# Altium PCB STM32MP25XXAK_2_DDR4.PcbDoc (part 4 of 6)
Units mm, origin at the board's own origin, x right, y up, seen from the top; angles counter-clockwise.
Board outline 120 x 79.6 mm, 4 copper layers (Top Layer, Signal Layer 1, Signal Layer 2, Bottom Layer), stack 1.614 mm thick; 243 components, 152 nets, 1304 pads, 784 vias.
Unrouted connection lines stored in the file: 6.
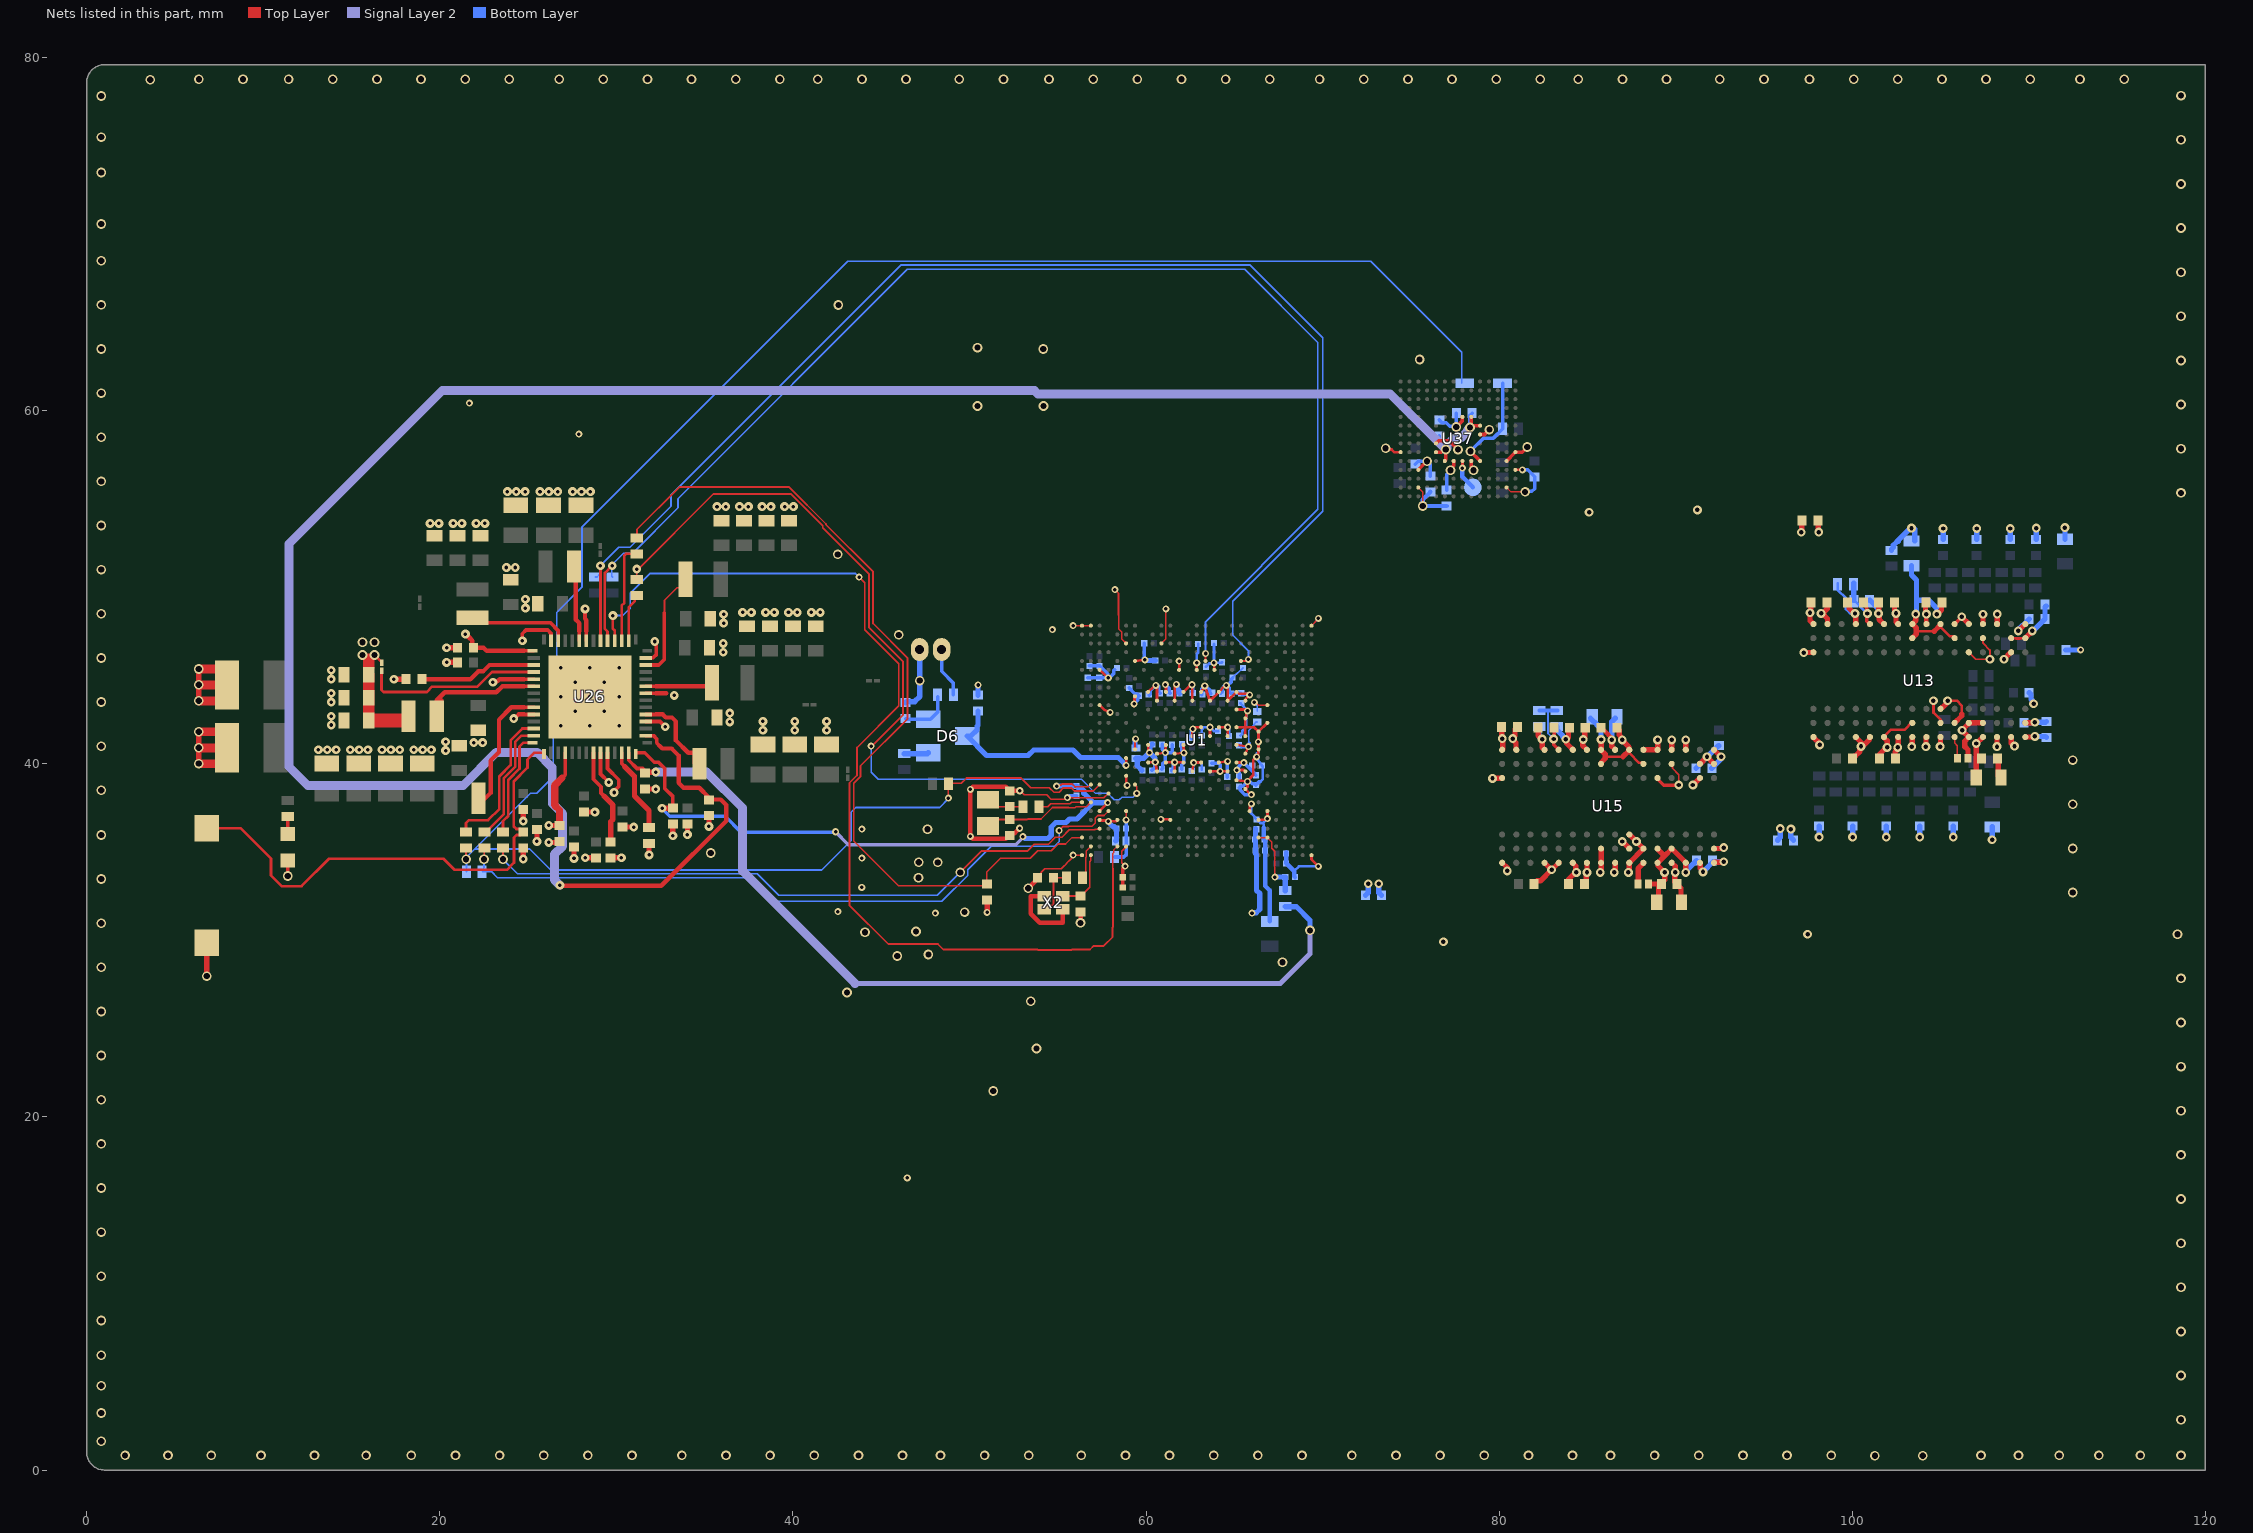
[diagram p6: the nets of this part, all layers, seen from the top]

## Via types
v1: diameter 0.55, hole 0.35, Top Layer to Bottom Layer, 256 vias
v2: diameter 0.4, hole 0.2, Top Layer to Bottom Layer, tented both sides, 235 vias
v3: diameter 0.5, hole 0.2, Top Layer to Bottom Layer, 146 vias
v4: diameter 0.5, hole 0.25, Top Layer to Bottom Layer, 143 vias
v5: diameter 0.5, hole 0.25, Top Layer to Bottom Layer, tented both sides, 4 vias

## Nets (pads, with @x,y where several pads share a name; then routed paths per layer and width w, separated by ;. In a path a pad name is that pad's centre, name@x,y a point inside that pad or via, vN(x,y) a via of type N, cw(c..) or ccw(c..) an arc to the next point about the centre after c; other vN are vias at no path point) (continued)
GND: B2.1 C1.1 C2.1 C3.1 C4.1 C5.1 C6.2 C7.1 C8.2 C9.1 C10.1 C11.1 C12.2 C13.1 C14.1 C15.1 C16.1 C17.1 C18.2 C19.1 C20.1 C21.1 C22.1 C23.1 C24.1 C26.1 C27.1 C28.1 C29.1 C30.1 C32.1 C33.1 C34.1 C35.1 C36.1 C37.1 C38.1 C39.1 C40.1 C41.1 C42.2 C43.1 C44.2 C45.1 C46.1 C47.2 C48.1 C49.1 C50.1 C51.1 C52.1 C53.1 C54.1 C55.1 C56.1 C58.1 C59.1 C60.1 C61.1 C62.1 C63.1 C64.1 C65.1 C66.1 C67.1 C68.1 C69.1 C70.2 C71.1 C72.1 C73.1 C74.1 C75.1 C76.1 C77.2 C79.1 C81.2 C82.1 C83.1 C84.1 C85.1 C86.2 C87.1 C88.1 C90.1 C91.2 C92.2 C117.1 C118.1 C128.1 C130.1 C142.2 C145.1 C146.1 C147.1 C148.1 C149.1 C150.1 C151.1 C152.1 C153.1 C154.1 C155.1 C156.1 C157.1 C158.1 C162.1 C170.1 C183.1 C184.1 C185.1 C186.1 C187.1 C188.1 C189.1 C190.2 C192.1 C193.1 C194.1 C195.1 C196.1 C197.1 C198.1 C199.1 C200.1 C201.1 C202.1 C203.1 C204.1 C205.1 C206.1 C207.1 C208.2 C209.1 C211.1 C212.1 C213.1 C214.1 C215.1 C216.1 C217.2 C218.1 C219.1 C220.1 C221.1 C225.1 C234.1 C235.1 C236.1 C237.1 C238.1 C239.1 C240.1 C244.1 C246.1 C248.1 C250.1 C251.1 C252.1 C253.1 C260.1 C1141.2 CN12.2 LD11.2 R57.1 R62.1 R75.1 R142.1 R147.1 R163.1 R174.1 U1.1A1 U1.1A3 U1.1A5 U1.1A7 U1.1A9 U1.1A11 U1.1B2 U1.1B4 U1.1B6 U1.1B8 U1.1B10 U1.1B12 U1.1E7 U1.1E9 U1.1F6 U1.1F8 U1.1F10 U1.1G1 U1.1G3 U1.1G5 U1.1G11 U1.1H2 U1.1H4 U1.1H12 U1.1J1 U1.1J3 U1.1J5 U1.1J7 U1.1J9 U1.1J11 U1.1K2 U1.1K4 U1.1K6 U1.1K8 U1.1K10 U1.1K12 U1.A1 U1.A2 U1.A27 U1.AC3 U1.AC5 U1.AC11 U1.AF6 U1.AG1 U1.AG27 U1.C6 U1.C10 U1.E7 U1.F3 U1.F12 U1.F14 U1.F16 U1.J7 U1.K3 U1.V6 U1.Y4 U13.A2 U13.A8 U13.B2 U13.C9 U13.D2 U13.D8 U13.E1 U13.E3 U13.E8 U13.E9 U13.F1 U13.G8 U13.H1 U13.H9 U13.K1 U13.K9 U13.M9 U13.N1 U13.N9 U13.T1 U13.T3 U15.A2 U15.A8 U15.B2 U15.C9 U15.D2 U15.D8 U15.E1 U15.E3 U15.E8 U15.E9 U15.F1 U15.G8 U15.H1 U15.H9 U15.K1 U15.K9 U15.M9 U15.N1 U15.N9 U15.T1 U15.T3 U26.9 U26.10 U26.18 U26.22 U26.27 U26.36 U26.41 U26.47 U26.52 U26.57 U37.A6 U37.C4 U37.E7 U37.G5 U37.H10 U37.J5 U37.K8 U37.N2 U37.N5 U37.P4 U37.P6 X2.2 X2.4 | length 240.8
  Top Layer w0.09: v2(55.55,38.085) 55.565,38.07 56.266,38.07 56.271,38.075 57.612,38.075 57.862,38.325 U1.Y4@57.875,38.325 ; U1.A1@56.375,47.825 U1.A2@56.875,47.825 ; 58.445,48.418 58.445,47.647 58.625,47.467 58.625,47.075 U1.C6@58.875,46.825 ; v2(58.816,34.213) 58.625,34.404 58.625,35.05 58.875,35.3 U1.AF6@58.875,35.325 ; U1.C10@60.875,46.825 61.125,47.075 v2(61.125,48.775) ; U37.N2@80.425,55.655 80.675,55.405 v1(81.475,55.405) ; U15.A8@92.208,35.257 v4@92.541,35.257 ; U13.A8@109.781,42.302 U13.A8@109.805,42.326
  Top Layer w0.1: v2(52.85,38.475) 52.882,38.475 53.114,38.244 54.372,38.244 54.622,37.994 55.458,37.994 v2(55.55,38.085) ; v1@53.243,33.041 v1(53.329,32.955) ; C92.2@53.859,33.546 53.859,33.648 54.264,34.053 55.189,34.053 55.279,34.144 55.291,34.144 55.496,34.349 55.496,34.361 55.77,34.635 55.77,34.639 55.875,34.744 v2(55.875,34.825) U1.AG1@56.375,34.825 ; v2(55.875,47.825) U1.A1@56.375,47.825 ; v2(58.24,49.865) 58.445,49.66 58.445,48.418 ; U1.A27@69.375,47.825 69.762,48.213 v2(69.762,48.238) ; v4@79.631,39.21 v4@79.635,39.205 ; v4@79.635,39.177 v4@79.635,39.205 ; v4@79.644,39.197 v4@79.635,39.205 ; U15.D2@89.781,40 89.823,39.958 89.823,39.747 90.181,39.39 90.181,38.8 v4@90.166,38.815 ; U13.E3@106.605,46.32 106.996,45.929 v4(107.803,45.929) 107.803,46.445 107.414,46.834 107.414,47.111 U13.D2@107.405,47.12
  Top Layer w0.15: U1.AC3@57.375,36.825 57.41,36.79 57.795,36.79 57.845,36.74 v2(57.872,36.74) 58.29,36.74 U1.AC5@58.375,36.825 ; U1.K3@57.375,43.325 57.643,43.057 v2(57.966,42.92) ; U1.F3@57.375,45.325 v2(57.862,44.875) ; U1.V6@58.875,39.325 58.875,38.893 58.925,38.843 v2(58.925,38.775) ; v2@59.325,43.275 59.35,43.3 59.35,43.613 ; v2(59.325,43.4) 59.35,43.613 ; U1.E7@59.375,45.825 v2(59.931,45.892) ; U1.J7@59.388,43.812 U1.J7@59.375,43.825 ; U1.1J1@60.125,40.075 v2(60.525,40.1) U1.1K2@60.625,39.575 ; U1.1G1@60.125,41.075 60.125,40.778 60.198,40.705 v2(60.198,40.638) ; U1.1A1@60.125,44.075 60.442,44.392 60.481,44.392 60.531,44.442 v2@60.555,44.442 ; v2(60.558,44.442) v2@60.555,44.442 ; U1.1H2@60.625,40.575 v2(61.092,40.638) U1.1G3@61.125,41.075 ; U1.1B2@60.625,43.575 60.625,44.371 v2@60.555,44.442 ; v2(60.841,36.854) 61.289,36.854 61.303,36.84 61.36,36.84 U1.AC11@61.375,36.825 ; U1.1J3@61.125,40.075 v2(61.625,40.089) ; U1.1A3@61.125,44.075 61.132,44.082 v2@61.132,44.466 ; U1.1K4@61.625,39.575 v2(61.625,40.089) ; U1.1H4@61.625,40.575 v2(62.15,40.625) U1.1G5@62.125,41.075 ; U1.1B4@61.625,43.575 61.625,44.405 v2(61.725,44.505) ; U1.F12@61.875,45.325 v2(61.875,45.825) ; U1.1J5@62.125,40.075 v2(61.625,40.089) ; U1.1A5@62.125,44.075 62.496,44.446 62.571,44.446 62.625,44.5 U1.1B6@62.625,43.575 ; U1.1K6@62.625,39.575 v2(62.7,40.075) U1.1J7@63.125,40.075 ; U1.1F6@62.625,41.575 62.625,41.95 v2(62.65,41.975) ; v2@62.657,41.975 62.718,41.975 62.818,42.075 U1.1E7@63.125,42.075 ; U1.F14@62.875,45.325 v2(62.875,45.725) ; U1.1A7@63.125,44.075 v2(63.328,44.412) U1.1B8@63.625,43.575 U1.1A9@64.125,44.075 64.448,44.398 64.538,44.398 64.586,44.446 64.625,44.407 U1.1B10@64.625,43.575 U1.1A11@65.125,44.075 65.147,44.075 65.25,43.972 65.818,43.972 65.865,43.925 65.865,43.894 65.64,43.669 65.64,43.59 U1.1B12@65.625,43.575 ; U1.1K8@63.625,39.575 v2(64.198,39.575) U1.1K10@64.625,39.575 ; U1.1F8@63.625,41.575 v2(63.625,42.075) ; v2@63.853,45.725 U1.F16@63.875,45.325 ; U1.1E9@64.125,42.075 v2(64.625,42.075) U1.1F10@64.625,41.575 ; U1.1G11@65.125,41.075 v2(65.806,40.972) U1.1H12@65.625,40.575 ; U1.AG27@69.375,34.825 69.375,34.59 v2(69.768,34.197) ; v1(73.575,57.875) 73.646,57.804 73.911,57.804 74.056,57.66 74.42,57.66 U37.A6@74.425,57.655 ; U37.P4@80.925,56.655 v2(81.325,56.655) ; v4@104.606,43.575 104.606,42.9 105.006,42.5 U13.G8@105.006,42.325 ; U13.B2@109.005,47.12 109.282,47.12 109.303,47.099 109.501,47.099 109.523,47.12 U13.A2@109.801,47.12 ; 59.35,43.613 59.35,43.825 U1.J7@59.375,43.825 ; 59.35,43.613 U1.J7@59.375,43.825
  Top Layer w0.16: U1.1J9@64.125,40.075 v2(64.625,40.143) ; U1.1J11@65.125,40.075 v2@65.5,40.075 ; v2(65.15,39.65) 65.55,39.65 U1.1K12@65.625,39.575
  Top Layer w0.2: v1@11.386,33.645 LD11.2@11.386,34.522 ; U26.27@31.67,46 32.079,46 32.27,46.191 32.27,46.91 v3@32.316,46.956 ; v3(32.17,46.93) v3@32.227,46.873 ; C248.1@58.683,33.002 C250.1@58.683,33.572 58.683,34.08 v2(58.816,34.213) ; U37.C4@75.425,56.655 75.875,57.105 75.885,57.105 v1(75.925,57.145) ; U37.E7@76.425,58.155 76.575,58.305 77.17,58.305 v1(77.675,57.8) ; v1(77.25,56.63) 77.25,56.718 77.425,56.893 U37.G5@77.425,57.155 ; v1(77.575,59.08) 77.925,59.43 U37.H10@77.925,59.655 ; U37.J5@78.425,57.155 78.425,56.85 78.55,56.725 v1(78.55,56.63) ; U37.K8@78.925,58.655 79.175,58.655 v1(79.45,58.93) ; U37.N5@80.425,57.155 U37.P6@80.925,57.655 81.305,57.655 v1(81.6,57.95) ; C85.1@81.991,33.193 C85.1@81.991,33.218 ; U15.E3@88.981,39.2 88.981,39.126 89.319,38.787 90.167,38.787 v4@90.181,38.8 ; U13.F1@105.806,47.925 v4@106.206,48.325
  Top Layer w0.21: v3(24.675,46.975) 24.675,47.375 24.88,47.58 26.109,47.58 26.3,47.389 U26.41@26.3,46.97 ; 24.775,42.8 U26.52@25.33,42.8 ; 24.775,44.8 U26.47@25.33,44.8 ; U26.36@28.3,46.97 28.3,47.525 ; U26.9@29.1,40.63 29.1,39.42 v3(29.568,38.952) ; U26.10@29.5,40.63 29.5,39.734 30.135,39.099 30.135,38.72 29.87,38.456 v3(29.87,38.377) ; U26.18@31.67,42.4 32.472,42.4 v3(32.772,42.1) ; U26.22@31.67,44 32.225,44
  Top Layer w0.25: v3(23.008,44.625) 23.056,44.673 23.257,44.673 23.384,44.8 24.775,44.8 ; v3(24.187,42.563) 24.221,42.563 24.459,42.8 24.775,42.8 ; v3(28.225,48.775) 28.225,48.214 28.3,48.139 28.3,47.525 ; 32.225,44 32.83,44 ; v3@32.757,42.1 v3(32.772,42.1) ; v2(52.841,36.352) 52.569,36.08 52.415,36.08 C86.2@52.285,35.95 52.26,35.95 52.061,35.75 50.196,35.75 v2(50.05,35.897) v2(50.05,38.554) 50.196,38.7 52.06,38.7 C81.2@52.285,38.475 v2(52.85,38.475) ; v1(53.329,32.955) 53.729,33.355 53.729,33.416 C92.2@53.859,33.546 ; X2.2@54.234,32.51 53.467,32.51 53.467,31.513 53.987,30.993 55.284,30.993 X2.4@55.284,31.76 ; v1(56.293,30.993) C90.1@56.293,31.61 ; C63.1@85.756,42.025 85.831,42.025 86.176,41.68 86.176,41.652 86.307,41.52 86.336,41.52 86.342,41.513 v4@86.342,41.388 ; U13.H1@104.206,47.925 v4@104.206,48.475
  Top Layer w0.3: v1@6.347,40.012 v1@6.347,41.812 ; v1@6.347,43.574 v1@6.347,45.374 ; B2.1@6.795,29.854 6.795,27.98 v1(6.8,27.975) ; v3(17.395,44.79) C43.1@18.055,44.79 ; v3(20.385,45.75) C40.1@20.995,45.75 ; v3(20.385,46.575) C39.1@20.995,46.575 ; v3@24.725,36.81 C217.2@24.725,37.42 ; v3@24.727,34.58 C155.1@24.727,35.185 ; v3(25.5,35.61) C154.1@25.5,36.215 ; v3(26.165,35.55) C142.2@26.775,35.55 ; v3@27.6,34.69 C1141.2@27.6,35.3 ; C153.1@28.175,37.27 v3(28.785,37.27) ; v3(28.24,34.68) C91.2@28.85,34.68 ; C208.2@29.675,34.68 v3(30.285,34.68) ; C209.1@30.35,36.42 v3(30.985,36.42) ; C156.1@31.625,38.57 v3(32.235,38.57) ; v3(31.85,34.84) R57.1@31.85,35.5 ; v3(33.2,35.93) C189.1@33.2,36.59 ; v3(34.025,35.99) C188.1@34.025,36.59 C188.1@34.025,36.65 ; v3(35.245,36.46) 35.248,36.462 35.248,37.062 C190.2@35.25,37.065 ; v2@50.979,31.565 v2(51,31.586) C33.1@51,32.3 ; v4@79.635,39.177 79.646,39.188 80.168,39.188 U15.T3@80.181,39.2 ; C60.1@80.106,42.075 80.143,42.038 80.143,41.463 v4@80.181,41.425 ; v4(80.178,41.429) 80.201,41.406 80.201,40.851 80.193,40.843 80.193,40.826 U15.T1@80.212,40.807 ; C85.1@81.991,33.218 82.146,33.373 82.347,33.373 v4(82.978,34.004) ; C61.1@82.215,42.05 82.215,41.603 82.44,41.378 82.44,40.931 82.571,40.8 U15.N1@82.581,40.8 ; U15.N9@82.581,34.4 82.977,34.004 82.981,34 U15.M9@83.381,34.4 ; v4@84.75,41.394 v4(84.766,41.379) ; C84.1@84.774,33.197 84.774,33.222 84.942,33.39 84.942,33.812 84.981,33.85 U15.K9@84.981,34.4 ; C62.1@84.856,42.025 84.856,41.499 84.735,41.379 84.732,41.382 84.732,41.039 U15.K1@84.974,40.797 ; v4@86.342,41.388 86.381,41.35 86.381,41 U15.H1@86.581,40.8 ; v4@86.531,33.85 86.581,33.9 U15.H9@86.581,34.4 ; v4@86.981,35.6 U15.G8@87.381,35.2 ; U15.F1@88.181,40.8 88.981,40.8 v4@88.981,41.35 ; R75.1@88.475,33.193 C83.1@89.149,33.193 ; C88.1@88.906,32.175 89.031,32.3 89.031,33.075 C83.1@89.149,33.193 ; U15.E8@88.981,35.184 89.375,34.79 89.375,34.784 ; U15.E9@88.991,34.4 89.375,34.784 ; U15.E9@89,34.381 89,34.231 89.381,33.85 89.381,33.425 C83.1@89.149,33.193 ; C83.1@89.186,33.195 89.184,33.193 C83.1@89.149,33.193 ; U15.D8@89.781,35.19 89.375,34.784 ; U15.D8@89.781,35.2 90.581,34.4 v4@90.581,33.85 ; U15.B2@91.381,40 91.781,40.4 U15.A2@92.181,40 ; U15.A8@92.181,35.2 v4@92.681,35.2 ; v5(97.118,53.124) 97.136,53.142 97.136,53.755 C151.1@97.155,53.774 ; v4(97.253,46.304) 97.789,46.304 U13.T3@97.805,46.32 ; C56.1@97.68,49.145 97.651,49.116 97.662,49.105 97.662,48.606 v5(97.612,48.556) 97.612,48.113 U13.T1@97.805,47.92 ; C54.1@99.73,49.15 99.835,49.045 99.835,48.81 100.112,48.533 100.158,48.533 100.205,48.486 U13.N1@100.205,47.92 ; C66.1@100.036,40.299 100.036,40.342 100.123,40.429 100.166,40.429 100.437,40.699 100.437,40.862 v4@100.475,40.9 ; U13.N9@100.205,41.52 100.532,41.193 v4@100.532,40.993 ; v4@100.638,41.1 100.706,41.1 100.986,41.38 100.986,41.505 U13.M9@101.006,41.525 ; C53.1@102.4,49.15 102.4,48.606 v4(102.483,48.523) 102.483,48.042 U13.K1@102.605,47.92 ; C67.1@102.431,40.324 102.431,40.668 102.481,40.718 102.481,40.825 102.606,40.95 U13.K9@102.606,41.525 ; C55.1@104.156,49.15 104.156,48.525 v4@104.206,48.475 ; v4@104.181,40.975 104.181,41.5 U13.H9@104.206,41.525 ; v4@106.206,48.325 U13.E1@106.612,47.918 ; R62.1@106.556,40.325 106.556,40.8 106.381,40.975 106.381,41.3 106.606,41.525 106.231,41.9 106.606,42.275 106.606,42.325 U13.D8@107.406,42.325 ; v4(108.203,40.979) 108.205,40.981 U13.C9@108.205,41.52 ; C65.1@108.206,40.375 108.273,40.308 108.273,39.333 C73.1@108.406,39.2 ; U13.A8@109.806,42.325 110.331,42.325 v4@110.356,42.35 ; U13.A2@109.806,47.125 v4@110.206,47.525
  Top Layer w0.5: v1@6.353,40.006 C18.2@7.936,40.006 ; v1@6.353,40.906 C18.2@7.936,40.906 ; v1@6.353,41.818 C18.2@7.936,41.818 ; v1@6.353,43.568 C42.2@7.936,43.568 ; v1@6.353,44.468 C42.2@7.936,44.468 ; v1@6.353,45.38 C42.2@7.936,45.38
  Bottom Layer w0.1: C10.1@64.9,44.885 65.085,45.07 65.114,45.07 65.352,45.308 65.375,45.308 C238.1@65.5,45.433 ; v2(65.806,40.972) v2@65.844,41.01 ; 65.844,41.178 65.814,41.208 65.814,41.891 66.1,42.176 66.1,42.225 66.25,42.375 R174.1@66.299,42.375
  Bottom Layer w0.15: v2(59.931,45.892) v2@59.935,45.896 ; C4.1@62.592,39.603 62.683,39.694 62.683,40.058 v2(62.7,40.075) 63.066,40.075 63.154,39.987 C5.1@63.154,39.672 ; v2(62.875,45.725) 62.875,46.219 62.95,46.294 C195.1@62.95,46.787 ; C52.1@63.162,41.607 63.162,41.944 63.293,42.075 v2(63.625,42.075) 63.844,41.856 C1.1@64.083,41.856 ; C11.1@63.4,45.5 63.586,45.686 63.807,45.686 v2@63.859,45.738 ; v2(63.85,45.725) 64.278,45.725 C69.1@64.305,45.752 ; v2@63.85,45.775 C239.1@63.85,46.787 ; v2(64.625,42.075) 64.706,41.994 C2.1@64.705,41.579 ; 68.39,33.919 68.669,34.197 v2(69.768,34.197) ; R147.1@99.182,50.229 99.182,49.846 99.639,49.389 99.639,48.768 99.874,48.533 v4@100.158,48.533
  Bottom Layer w0.2: v2(55.55,38.085) 55.663,38.198 C234.1@56.064,38.198 ; C237.1@56.696,44.88 C236.1@57.345,44.88 ; C192.1@56.8,45.55 C201.1@57.375,45.55 57.825,45.1 57.825,44.912 v2(57.862,44.875) 57.862,44.894 57.881,44.914 57.974,44.914 58.163,45.103 58.163,45.282 C16.1@58.216,45.334 ; C236.1@57.35,44.875 v2(57.862,44.875) ; C240.1@59.05,44.3 59.37,43.98 59.484,43.98 59.534,43.93 C220.1@59.534,43.856 ; v2(59.325,43.4) 59.325,43.408 59.534,43.617 59.534,43.781 C220.1@59.609,43.856 C220.1@59.534,43.931 ; v2@59.902,45.948 C17.1@59.902,46.829 ; C45.1@60.173,43.895 60.235,43.957 60.235,44.124 60.248,44.137 60.248,44.139 60.551,44.442 v2(60.558,44.442) ; C71.1@60.34,39.635 60.491,39.786 60.491,40.066 v2(60.525,40.1) ; v2@60.624,44.485 60.726,44.383 60.726,44.075 C51.1@60.813,43.988 ; C72.1@60.905,39.698 60.956,39.749 60.956,40.021 61.092,40.157 v2(61.092,40.638) ; C46.1@60.915,41.105 60.915,40.815 v2(61.092,40.638) ; v2@61.132,44.466 61.132,44.444 61.302,44.274 61.302,44.062 C49.1@61.377,43.987 ; C12.2@61.467,39.624 61.542,39.699 61.542,39.952 61.625,40.035 v2(61.625,40.089) ; C47.2@61.476,41.081 61.476,40.694 61.42,40.638 v2(61.092,40.638) ; C74.1@62.03,39.683 62.03,39.955 62.15,40.075 v2(62.15,40.625) 62.038,40.737 C48.1@62.038,41.107 ; C7.1@62.581,44.08 62.636,44.08 62.636,44.483 v2@62.625,44.494 ; C6.2@63.156,43.924 63.156,44.24 v2(63.328,44.412) 63.366,44.374 63.421,44.374 63.6,44.195 63.6,44.059 C8.2@63.675,43.984 ; C59.1@63.714,40.036 64.111,40.036 64.198,39.949 v2(64.198,39.575) ; C68.1@64.239,43.997 64.314,44.072 64.314,44.284 64.437,44.408 64.548,44.408 v2@64.586,44.446 ; C58.1@64.607,39.247 64.607,40.125 v2(64.625,40.143) ; C10.1@64.915,44.871 64.84,44.796 64.84,44.663 64.623,44.446 v2@64.586,44.446 ; C82.1@65.125,41.05 65.355,41.05 65.433,40.972 v2(65.806,40.972) ; C76.1@65.274,39.198 65.274,39.526 v2(65.15,39.65) 65.15,39.704 65.25,39.804 65.25,39.848 65.477,40.075 65.53,40.075 66.15,39.455 66.15,39.425 C77.2@66.225,39.35 ; v2@65.844,41.01 65.844,41.178 ; v2@65.886,43.946 65.865,43.925 65.851,43.939 65.436,43.939 65.375,44 64.804,44 64.8,43.996 64.725,44.071 64.725,44.307 v2@64.586,44.446 ; C118.1@75.26,56.98 75.425,57.145 v1(75.925,57.145) 76.11,56.96 C79.1@76.11,56.305 ; C9.1@76.615,59.48 76.77,59.325 77.008,59.325 77.208,59.126 77.529,59.126 v1(77.575,59.08) C117.1@77.575,59.864 ; C130.1@77.027,55.505 77.027,56.407 v1(77.25,56.63) ; v2(81.325,56.655) 81.615,56.655 C128.1@82.015,56.255 82.015,55.592 81.858,55.435 81.505,55.435 v1(81.475,55.405)
  Bottom Layer w0.25: C253.1@67.941,34.367 68.39,33.919 68.39,33.638 C251.1@68.44,33.588 ; C253.1@67.941,34.385 C246.1@67.941,34.986
  Bottom Layer w0.3: C14.1@46.382,43.465 46.439,43.522 46.897,43.522 47.189,43.814 CN12.2@47.189,46.897 ; C87.1@50.485,43.888 v2(50.485,44.466) ; v2(57.872,36.74) 57.891,36.721 57.891,36.682 58.133,36.44 58.216,36.44 C244.1@58.325,36.331 58.325,35.675 C235.1@58.275,35.625 ; C70.2@59.775,39.625 59.506,39.894 59.506,40.25 59.456,40.3 C225.1@59.425,40.3 59.451,40.326 59.886,40.326 v2(60.198,40.638) ; v2@59.902,45.948 59.931,45.919 v2(59.931,45.892) 59.958,45.892 60,45.85 C196.1@60.525,45.85 ; C44.2@60.351,41.105 60.217,40.971 60.217,40.657 v2(60.198,40.638) ; v2(60.525,40.1) 60.506,40.119 60.506,40.33 v2(60.198,40.638) ; v2(61.725,44.505) 61.725,44.478 61.75,44.453 61.75,44.284 61.875,44.159 61.875,44.025 C50.1@61.9,44 ; C3.1@62.6,41.475 62.604,41.479 62.604,41.901 62.65,41.948 v2(62.65,41.975) ; v2@65.984,31.527 v2(66.003,31.546) 66.023,31.565 66.243,31.565 66.449,31.771 66.449,32.645 66.258,32.836 66.258,34.855 66.2,34.914 C252.1@66.2,36.324 ; v4(73.189,33.206) 73.189,32.706 C221.1@73.339,32.556 ; v1(75.5,62.9) v1@75.51,62.91 ; R142.1@82.239,42.119 82.239,41.604 v4(82.44,41.403) ; v4(86.378,41.354) 86.378,42.379 C194.1@86.575,42.577 ; v4(90.578,33.854) 90.578,33.929 C219.1@91.178,34.529 ; C205.1@91.153,39.754 v4@91.778,40.379 ; v4(91.778,40.404) v4@91.778,40.379 ; C203.1@92.453,41.029 92.428,41.029 v4@91.778,40.379 ; v4(96.528,36.304) 96.528,35.829 C218.1@96.678,35.679 ; v4(98.128,35.854) C216.1@98.128,36.479 ; v4(100.028,35.854) C215.1@100.028,36.479 ; v4(101.928,35.854) C214.1@101.928,36.479 ; R163.1@102.228,52.098 102.228,52.154 102.327,52.253 102.327,52.378 102.553,52.604 102.603,52.604 102.578,52.629 103.301,53.352 v4(103.36,53.352) 103.499,53.352 103.546,53.305 C150.1@103.546,52.628 ; v4(103.828,35.854) C213.1@103.828,36.479 ; C149.1@105.153,52.704 v4(105.153,53.329) ; v4(105.728,35.854) C212.1@105.728,36.479 ; C148.1@107.053,52.704 v4(107.053,53.329) ; v4(107.928,35.704) C211.1@107.928,36.429 ; C147.1@108.953,52.704 v4(108.953,53.329) ; C198.1@109.728,42.329 110.328,42.329 v4(110.353,42.354) 110.953,42.354 C197.1@111.003,42.402 ; C185.1@110.028,44.029 110.133,43.924 110.133,43.666 110.206,43.593 110.206,43.557 110.306,43.457 v4@110.306,43.403 ; v4(110.203,47.529) 110.253,47.529 110.928,48.204 110.928,48.879 C158.1@110.99,48.942 ; C146.1@110.428,52.729 v4(110.428,53.354) ; C145.1@112.053,52.728 v4(112.053,53.379) ; C170.1@112.103,46.454 112.939,46.454 v2(112.945,46.46)
  other v1: 101.286,0.805 104,0.805 2.175,0.83 4.6,0.83 7.05,0.83 9.875,0.83 12.9,0.83 15.825,0.83 18.386,0.83 20.886,0.83 23.386,0.83 25.886,0.83 28.386,0.83 30.886,0.83 33.711,0.83 36.211,0.83 38.711,0.83 41.211,0.83 43.711,0.83 46.211,0.83 48.361,0.83 50.861,0.83 53.361,0.83 56.336,0.83 58.836,0.83 61.336,0.83 63.836,0.83 66.336,0.83 68.836,0.83 71.661,0.83 74.161,0.83 76.661,0.83 79.161,0.83 81.661,0.83 84.161,0.83 86.311,0.83 88.811,0.83 91.311,0.83 93.811,0.83 96.311,0.83 98.811,0.83 107.3,0.83 109.425,0.83 111.725,0.83 113.975,0.83 116.325,0.83 118.625,0.83 0.825,1.625 118.625,2.85 0.825,3.225 0.825,4.775 118.625,5.35 0.825,6.5 118.625,7.85 0.825,8.475 118.625,10.35 0.825,10.975 118.625,12.85 0.825,13.475 118.625,15.35 0.825,15.975 118.625,17.85 0.825,18.475 118.625,20.35 0.825,20.975 51.35,21.475 118.625,22.85 0.825,23.475 53.8,23.875 118.625,25.35 0.825,25.975 53.467,26.55 43.063,27.05 118.625,27.85 0.825,28.475 67.73,28.759 45.909,29.117 47.672,29.202 118.428,30.35 44.087,30.462 46.975,30.5 0.825,30.975 49.725,31.6 112.495,32.71 0.825,33.475 47.112,33.546 11.387,33.648 47.125,34.425 48.2,34.42 35.35,34.945 112.495,35.21 0.825,35.975 47.625,36.3 112.495,37.71 0.825,38.5 6.348,40.014 112.495,40.21 6.348,40.914 0.825,41 6.348,41.814 0.825,43.5 6.348,43.576 6.348,44.476 47.189,44.713 6.348,45.376 0.825,46 45.995,47.305 0.825,48.5 0.825,51 42.535,51.865 0.825,53.5 118.625,55.35 0.825,56 118.625,57.85 0.825,58.5 50.45,60.275 54.195,60.275 118.625,60.35 0.825,61 118.625,62.85 0.825,63.5 54.175,63.5 50.45,63.575 118.625,65.35 0.825,66 42.575,65.995 118.625,67.85 0.825,68.5 118.625,70.35 0.825,70.575 118.625,72.85 0.825,73.5 118.625,75.35 0.825,75.5 0.825,77.825 118.625,77.85 3.6,78.75 6.35,78.775 8.85,78.775 11.436,78.775 13.936,78.775 16.436,78.775 18.936,78.775 21.436,78.775 23.936,78.775 26.761,78.775 29.261,78.775 31.761,78.775 34.261,78.775 36.761,78.775 39.261,78.775 41.411,78.775 43.911,78.775 46.411,78.775 49.425,78.775 51.925,78.775 54.511,78.775 57.011,78.775 59.511,78.775 62.011,78.775 64.511,78.775 67.011,78.775 69.836,78.775 72.336,78.775 74.836,78.775 77.336,78.775 79.836,78.775 82.336,78.775 84.486,78.775 86.986,78.775 89.486,78.775 92.5,78.775 95,78.775 97.586,78.775 100.086,78.775 102.586,78.775 105.086,78.775 107.586,78.775 110.086,78.775 112.911,78.775 115.411,78.775
  other v2: 46.475,16.55 48.075,31.55 42.551,31.633 43.9,33 43.902,34.655 43.902,36.305 65.54,40.075 65.87,43.91 64.55,44.448 61.1,44.49 62.606,44.48 54.694,47.6 27.875,58.675 21.675,60.437
  other v3: 24.722,34.61 27.6,34.64 24.725,36.76 20.325,40.75 13.124,40.798 13.625,40.798 14.126,40.798 14.924,40.798 15.425,40.798 15.926,40.798 16.724,40.798 17.225,40.798 17.726,40.798 18.524,40.798 19.025,40.798 19.526,40.798 21.924,41.202 22.425,41.202 20.325,41.25 38.304,41.9 40.104,41.9 41.904,41.9 26.85,42.15 28.5,42.15 30.15,42.15 13.85,42.2 36.42,42.375 38.304,42.401 40.104,42.401 41.904,42.401 13.85,42.7 36.42,42.875 27.675,42.975 29.325,42.975 13.85,43.5 26.85,43.8 28.5,43.8 30.15,43.8 33.28,43.875 13.85,44 27.675,44.625 29.325,44.625 13.85,44.8 13.85,45.3 26.85,45.45 28.5,45.45 30.15,45.45 36.05,46.325 36.05,46.825 36.075,47.975 36.075,48.475 37.15,48.575 37.65,48.575 38.45,48.575 38.95,48.575 39.75,48.575 40.25,48.575 41.05,48.575 41.55,48.575 24.85,48.823 24.85,49.323 23.775,51.123 24.276,51.123 19.45,53.623 19.951,53.623 20.75,53.623 21.251,53.623 22.05,53.623 22.551,53.623 35.7,54.575 36.2,54.575 36.975,54.575 37.475,54.575 38.25,54.575 38.75,54.575 39.525,54.575 40.025,54.575 23.824,55.425 24.325,55.425 24.826,55.425 25.674,55.425 26.175,55.425 26.676,55.425 27.524,55.425 28.025,55.425 28.526,55.425
  other v4: 76.844,29.925 97.475,30.35 84.978,33.854 86.528,33.854 89.378,33.854 92.728,35.254 86.978,35.604 90.178,38.804 79.628,39.179 102.578,40.929 104.178,40.979 100.5,40.99 88.978,41.354 106.228,41.904 110.276,43.405 104.603,43.579 106.203,48.329 104.203,48.479 100.158,48.517 85.1,54.256 91.234,54.385
HSE_IN: C90.2 U1.AG2 X2.1 | length 3.6
  Top Layer w0.1: X2.1@55.284,32.51 56.318,32.51 56.814,33.005 56.814,34.464 56.875,34.525 U1.AG2@56.875,34.825
HSE_OUT: R3.2 U1.AF2 | length 2
  Top Layer w0.09: 56.59,34.075 56.59,34.686 56.625,34.721 56.625,35.075 U1.AF2@56.875,35.325
  Top Layer w0.1: R3.2@56.409,33.546 56.59,33.727 56.59,34.075
I2C7.SCL: R261.1 U1.E15 U26.33 | length 74.8
  Top Layer w0.1: U1.E15@63.375,45.825 v2(63.375,46.25)
  Top Layer w0.15: U26.33@29.5,46.97 29.5,47.5 29.35,47.65 29.35,50.812 v3(29.763,51.225)
  Bottom Layer w0.1: R261.1@29.785,50.583 29.743,50.626 29.743,51.265 30.406,51.929 30.917,51.929 33.493,54.505 33.493,55.016 46.487,68.01 65.588,68.01 69.733,63.865 69.733,54.412 63.375,48.054 v2(63.375,46.25)
I2C7.SDA: R260.1 U1.E19 U26.34 | length 76.1
  Top Layer w0.1: U1.E19@65.375,45.825 v2@65.629,45.825
  Top Layer w0.15: U26.34@29.1,46.97 v3(29.1,51.225)
  Bottom Layer w0.1: R260.1@28.81,50.583 28.9,50.583 29.08,50.763 v3@29.08,51.228 ; v3@29.093,51.228 30.141,52.275 30.771,52.275 33.099,54.603 33.099,55.234 46.115,68.25 65.899,68.25 70.009,64.14 70.009,54.304 64.91,49.206 64.91,47.299 65.8,46.41 v2(65.8,45.915)
MP257_WAKEUP: U1.AF5 U26.32 | length 59.2
  Top Layer w0.09: 58.125,34.075 58.125,34.929 58.165,34.969 58.165,35.115 U1.AF5@58.375,35.325
  Top Layer w0.1: v2(43.751,50.58) 44.063,50.269 44.063,47.604 45.995,45.672 45.995,43.285 43.631,40.921 43.631,39.348 43.2,38.916 43.2,31.993 45.395,29.797 48.212,29.797 48.525,29.485 53.864,29.485 53.889,29.46 55.786,29.46 55.811,29.485 56.828,29.485 57.032,29.69 57.602,29.69 58.106,30.195 58.106,30.747 58.125,30.765 58.125,34.075
  Top Layer w0.15: v3(29.8,48.4) 29.8,47.653 29.9,47.553 U26.32@29.9,46.97
  Bottom Layer w0.1: v3@29.78,48.403 30.361,48.403 30.78,48.823 30.78,49.661 31.898,50.778 43.543,50.778 43.74,50.58 v2(43.751,50.58)
NetB2_2: B2.2 C155.2 U26.1 | length 28.3
  Top Layer w0.15: B2.2@6.795,36.354 8.721,36.354 10.438,34.637 10.438,33.673 11.036,33.075 12.162,33.075 13.713,34.625 20.219,34.625 20.845,33.999 23.799,33.999 24.2,34.4 24.2,35.825 24.347,35.972 24.554,35.972 C155.2@24.727,36.145 24.562,36.31 24.338,36.31 24.187,36.46 24.187,39.008 24.962,39.783 24.962,40.237 25.355,40.63 U26.1@25.9,40.63
NetC14_2: C14.2 D6.2 R66.2 | length 2.9
  Bottom Layer w0.2: C14.2@46.382,42.565 46.424,42.523 D6.2@47.673,42.523 47.792,42.523 48.192,42.923 R66.2@48.192,43.796
NetC15_2: C15.2 C252.2 C260.2 R11.2 U1.AB20 U1.AB22 U1.AC21 | length 8.8
  Top Layer w0.15: U1.AB20@65.875,37.325 65.875,37.607 65.95,37.682 v2@65.95,37.75 ; U1.AC21@66.375,36.825 v2@66.732,36.825
  Top Layer w0.16: U1.AB22@66.875,37.325 66.875,36.95 v2@66.9,36.925
  Bottom Layer w0.15: v2(65.969,37.735) 65.95,37.716 65.95,37.205 66.167,36.988 66.167,36.939 66.355,36.75 66.374,36.75 66.474,36.65 66.502,36.65 66.637,36.65 v2@66.875,36.889 ; 66.597,36.65 66.675,36.572 66.675,36.37
  Bottom Layer w0.25: 66.675,36.37 66.675,35.766 66.721,35.72 C15.2@66.721,35.716 ; C15.2@66.75,35.714 66.75,33.083 67,32.833 R11.2@67,31.075
  other v2: 66.875,36.9
NetC43_2: C43.2 U26.45 | length 6.7
  Top Layer w0.21: 24.775,45.6 U26.45@25.33,45.6
  Top Layer w0.25: C43.2@19.015,44.79 21.731,44.79 22.176,45.235 22.451,45.235 22.816,45.6 24.775,45.6
NetC54_2: C54.2 R146.1 R147.2 U13.M1 | length 3.4
  Top Layer w0.2: C54.2@100.63,49.15 100.785,48.995 100.785,48.886 100.818,48.853 100.818,48.559 v4@100.848,48.529 ; v4@100.828,48.476 100.828,48.079 100.982,47.925 U13.M1@101.006,47.925
  Bottom Layer w0.15: R146.1@100.095,49.275 v4@100.853,48.516
  Bottom Layer w0.3: R147.2@100.082,50.229 100.082,49.288 R146.1@100.095,49.275
  other v4: 100.86,48.517
NetC61_2: C61.2 R141.1 R142.2 U15.M1 | length 4.2
  Top Layer w0.2: v4@83.044,41.362 v4(83.088,41.406) ; C61.2@83.115,42.05 83.115,41.433 v4(83.088,41.406) ; U15.M1@83.374,40.797 83.088,41.083 v4(83.088,41.406)
  Bottom Layer w0.1: 82.79,43.023 82.768,43 82.768,41.726 v4(83.088,41.406)
  Bottom Layer w0.2: R142.2@82.271,43.023 82.79,43.023 R141.1@83.268,43.023 R141.1@83.31,43.023
NetC79_2: C79.2 C130.2 U37.C2 | length 3.5
  Top Layer w0.09: U37.C2@75.425,55.655 75.675,55.405 v1(75.675,54.605)
  Bottom Layer w0.25: C79.2@76.11,55.405 75.675,54.97 v1(75.675,54.605) C130.2@77.027,54.605
NetC81_1: C81.1 R64.2 X1.1 | length 2.1
  Top Layer w0.1: X1.1@51.059,37.975 51.459,37.575 C81.1@52.285,37.575 R64.2@53.035,37.575
NetC92_1: C92.1 R3.1 X2.3 | length 2.9
  Top Layer w0.1: X2.3@54.234,31.76 54.461,31.987 54.694,31.987 54.759,32.052 C92.1@54.759,33.546 R3.1@55.509,33.546
NetC208_1: C208.1 U26.8 | length 5.4
  Top Layer w0.21: U26.8@28.7,40.63 28.7,39.134 29.125,38.709 29.125,38.345 29.298,38.172
  Top Layer w0.3: 29.298,38.172 29.8,37.67 29.8,36.843 29.675,36.718 C208.1@29.675,35.705
NetC225_2: C225.2 U1.R7 | length 1.1
  Top Layer w0.1: U1.R7@59.375,40.825 v2@59.375,41.41
  Bottom Layer w0.1: C225.2@59.375,40.95 C225.2@59.425,40.9
  Bottom Layer w0.3: C225.2@59.375,40.95 v2@59.375,41.41
  other v2: 59.41,41.41
NetC235_2: C235.2 C244.2 R267.1 U1.AB6 | length 3.2
  Top Layer w0.09: v2(58.875,36.825) U1.AB6@58.875,37.325
  Bottom Layer w0.2: R267.1@58.223,34.723 58.734,34.723 58.875,34.864 C235.2@58.875,35.625 C244.2@58.875,36.331 v2(58.875,36.825)
NetC251_2: C251.2 R286.2 U1.AE21 U1.AE22 | length 4.3
  Top Layer w0.09: U1.AE21@66.375,35.825 U1.AE22@66.875,35.825 ; U1.AE22@66.902,35.798 67.125,35.575 67.125,35.221 67.295,35.052 67.295,33.593 v2(67.3,33.588)
  Top Layer w0.1: U1.AE22@66.875,35.825 U1.AE22@66.902,35.798
  Bottom Layer w0.3: v2(67.3,33.588) C251.2@67.89,33.588 R286.2@67.89,32.815
NetCN12_1: CN12.1 R66.1 | length 3.2
  Bottom Layer w0.2: CN12.1@48.425,46.801 48.425,45.241 49.083,44.583 R66.1@49.083,43.917
NetD6_1: D6.1 R67.1 | length 1.4
  Bottom Layer w0.3: R67.1@46.3,40.575 47.625,40.575 D6.1@47.673,40.623
NetD7_1: D7.1 R248.1 U37.K5 | length 5.7
  Top Layer w0.2: v1(78.375,57.705) U37.K5@78.925,57.155
  Bottom Layer w0.2: v1(78.375,57.705) 79.125,58.455 79.682,58.455 R248.1@80.207,58.98 80.207,61.55 D7.1@80.195,61.563
NetL1_1: L1.1 U26.37 | length 4.2
  Top Layer w0.21: U26.37@27.9,46.97 27.9,47.525
  Top Layer w0.25: L1.1@27.7,51.135 27.7,48.173 27.9,47.973 27.9,47.525
NetL2_1: L2.1 U26.26 | length 6
  Top Layer w0.09: 32.725,48.56 32.725,49.26 33.433,49.968 33.56,49.968 33.915,50.323 L2.1@33.915,50.45
  Top Layer w0.2: U26.26@31.917,45.6 32.4,45.6 32.725,45.925 32.725,48.56
NetL3_1: L3.1 U26.40 | length 5.9
  Top Layer w0.15: L3.1@21.698,48.162 L3.1@21.85,48.01
  Top Layer w0.21: L3.1@21.85,48.275 22.135,47.99 23.91,47.99 26.265,47.99 26.7,47.555 U26.40@26.7,46.97
NetL4_1: L4.1 U26.23 | length 3.8
  Top Layer w0.15: L4.1@35.36,43.885 L4.1@35.36,44.4
  Top Layer w0.21: U26.23@31.67,44.4 32.225,44.4
  Top Layer w0.25: 32.225,44.4 35,44.4
NetL5_1: L5.1 U26.48 | length 7.2
  Top Layer w0.15: L5.1@19.618,42.448 L5.1@19.87,42.7 ; L5.1@20.09,42.585 L5.1@20.09,43.1
  Top Layer w0.21: 24.775,44.4 U26.48@25.33,44.4
  Top Layer w0.25: 19.825,43.6 20.275,44.05 23.2,44.05 23.55,44.4 24.775,44.4 ; L5.1@20.09,43.1 20.09,43.615
NetL6_1: L6.1 U26.19 | length 4.9
  Top Layer w0.21: U26.19@31.67,42.8 32.225,42.8
  Top Layer w0.25: 32.225,42.8 32.623,42.8 32.798,42.625 33.15,42.625 33.375,42.4 33.375,41.325 34.071,40.629 34.425,40.629 34.43,40.624 L6.1@34.43,40.025
NetL7_1: L7.1 U26.51 | length 7.4
  Top Layer w0.21: 24.775,43.2 U26.51@25.33,43.2
  Top Layer w0.25: L7.1@22.425,38.425 L7.1@22.425,38.669 ; L7.1@22.475,37.95 22.875,38.35 22.875,40.184 23.35,40.659 23.35,42.503 24.047,43.2 24.775,43.2
NetLD11_1: LD11.1 R210.2 | length 1
  Top Layer w0.2: LD11.1@11.386,36.022 R210.2@11.386,37.015
NetR2_2: R2.2 U26.56 | length 6.1
  Top Layer w0.15: R2.2@23.58,36.145 23.58,36.76 23.875,37.055 23.875,39.091 24.512,39.728 24.512,40.985 24.727,41.2 U26.56@25.255,41.2
NetR46_2: R46.2 U26.30 | length 2.8
  Top Layer w0.15: U26.30@30.7,46.97 30.7,48.87 31.032,49.202 31.032,49.43 R46.2@31.15,49.548
NetR57_2: R57.2 U26.12 | length 4.9
  Top Layer w0.21: U26.12@30.3,40.63 30.3,40.016 30.47,39.845
  Top Layer w0.3: 30.47,39.845 31.025,39.291 31.025,38.174 31.85,37.349 R57.2@31.85,36.4
NetR59_2: R59.2 U26.54 | length 8.5
  Top Layer w0.15: R59.2@21.48,36.145 21.48,36.64 21.65,36.81 22.736,36.81 23.375,37.449 23.375,39.298 24.012,39.935 24.012,41.335 24.677,42 U26.54@25.33,42
NetR60_2: R60.2 U26.55 | length 7.1
  Top Layer w0.15: R60.2@22.53,36.145 22.604,36.145 23.625,37.166 23.625,39.194 24.262,39.832 24.262,41.232 24.631,41.6 U26.55@25.33,41.6
NetR62_2: R62.2 U13.F9 | length 1.3
  Top Layer w0.09: U13.F9@105.806,41.525 105.806,41.175 105.956,41.025 R62.2@105.956,40.325
NetR75_2: R75.2 U15.F9 | length 1.3
  Top Layer w0.3: R75.2@87.875,33.193 87.875,34.069 88.181,34.374 U15.F9@88.181,34.4
NetR81_2: R81.2 U26.31 | length 5.7
  Top Layer w0.15: U26.31@30.3,46.97 30.3,48.973 30.45,49.123 30.45,51.81 30.538,51.898 R81.2@31.163,51.898
NetR174_2: R174.2 U1.K22 | length 1.4
  Top Layer w0.1: v2(66.135,43.486) 66.212,43.486 66.374,43.325 U1.K22@66.875,43.325
  Bottom Layer w0.1: v2(66.135,43.486) 66.135,43.454 66.3,43.289 R174.2@66.3,42.975
NetTP21_1: TP21.1 U37.H5 | length 1.7
  Top Layer w0.15: v2(77.925,56.755) U37.H5@77.925,57.155
  Bottom Layer w0.25: v2(77.925,56.755) 77.925,56.256 TP21.1@78.516,55.665
NRST: C33.2 R81.1 U1.AE1 | length 49.7
  Top Layer w0.09: 55.444,35.457 55.812,35.825 U1.AE1@56.375,35.825
  Top Layer w0.1: R81.1@31.163,52.798 31.163,53.273 33.565,55.675 39.786,55.675 41.873,53.588 41.873,53.551 44.541,50.883 44.541,47.949 46.497,45.992 46.497,42.556 43.821,39.879 43.821,39.269 43.443,38.89 43.443,35.633 45.978,33.097 50.897,33.097 C33.2@51,33.2 50.975,33.225 50.975,33.875 51.758,34.658 53.449,34.658 53.863,35.073 54.632,35.073 55.016,35.457 55.444,35.457
NRSTC1MS: D7.2 R27.1 R59.1 R272.1 U1.W3 | length 123.2
  Top Layer w0.09: 56.11,38.46 57.01,38.46 U1.W3@57.375,38.825
  Top Layer w0.1: R59.1@21.48,35.245 21.475,35.24 21.475,34.625 v1@21.49,34.61 ; v2(48.805,38.061) R27.1@48.805,38.872 48.805,38.904 49.542,38.904 49.831,39.194 49.936,39.194 49.938,39.192 50.559,39.192 50.561,39.194 52.93,39.194 53.474,38.65 54.531,38.65 54.787,38.394 55.077,38.394 55.319,38.635 55.764,38.635 55.939,38.46 56.11,38.46
  Bottom Layer w0.1: R272.1@21.505,33.882 21.505,34.595 21.49,34.61 21.49,34.694 21.972,35.176 ; v2(48.805,38.061) 48.805,38.016 48.314,37.526 43.556,37.526 43.288,37.258 43.288,35.651 41.626,33.989 26.279,33.989 25.092,35.176 21.972,35.176 ; D7.2@77.88,61.563 77.88,63.32 72.735,68.465 43.114,68.465 28.049,53.4 28.049,50.003 26.618,48.572 26.618,45.92 26.431,45.733 26.431,39.267 25.501,38.337 25.133,38.337 21.972,35.176
  other v1: 21.49,34.6
OSC32_IN: C86.1 U1.AA2 X1.2 | length 6.4
  Top Layer w0.09: 55.625,37.525 56,37.525 56.05,37.575 56.625,37.575 U1.AA2@56.875,37.825
  Top Layer w0.1: X1.2@51.059,36.475 51.434,36.85 53.271,36.85 53.296,36.875 54.052,36.875 54.702,37.525 55.625,37.525
OSC32_OUT: R64.1 U1.AA1 | length 2.5
  Top Layer w0.09: 56.05,37.825 U1.AA1@56.375,37.825
  Top Layer w0.1: R64.1@53.935,37.575 54.436,37.575 54.597,37.735 55.695,37.735 55.784,37.825 56.05,37.825
PMIC_WAKEUPn: R46.1 U1.W7 | length 46.6
  Top Layer w0.09: U1.W7@59.375,38.825 59.375,38.802 59.475,38.702 v2(59.475,38.325)
  Top Layer w0.1: R46.1@31.15,50.448 31.15,50.942 35.501,55.293 39.879,55.293 41.683,53.488 41.683,53.37 44.316,50.738 44.316,47.708 46.24,45.785 46.24,42.779 44.461,41 v2(44.43,41)
  Bottom Layer w0.09: v2(44.43,41) 44.43,39.527 44.833,39.123 56.341,39.123 57.139,38.325 57.851,38.325 58.206,37.97 58.492,37.97 58.637,38.115 59.265,38.115 v2(59.475,38.325)
  other v3: 31.15,51.033
PWR_CPU_ON: R60.1 R272.2 U1.AB4 | length 40.2
  Top Layer w0.09: 55.627,36.457 56.927,36.457 57.125,36.655 57.125,36.929 57.271,37.075 57.625,37.075 U1.AB4@57.875,37.325
  Top Layer w0.095: 55.57,36.455 55.625,36.455
  Top Layer w0.1: v1(22.5,34.6) 22.514,34.614 22.514,35.229 R60.1@22.53,35.245 ; v2(55.077,36.225) 55.307,36.455 55.57,36.455
  Bottom Layer w0.1: R272.2@22.405,33.882 22.936,33.882 23.265,33.553 37.33,33.553 38.666,32.217 48.438,32.217 49.9,33.679 49.9,34.006 51.228,35.335 54.815,35.335 55.083,35.603 v2@55.083,36.219 ; R272.2@22.471,34.068 22.5,34.097 v1(22.5,34.6)
PWR_ON: R2.1 U1.AD3 | length 36.9
  Top Layer w0.09: 56.084,36.26 57.09,36.26 57.128,36.298 57.348,36.298 U1.AD3@57.375,36.325
  Top Layer w0.1: v1(23.575,34.6) 23.58,34.605 R2.1@23.58,35.245 ; v1(49.475,33.855) 50.678,35.058 53.276,35.058 53.671,35.453 54.474,35.453 54.865,35.844 55.241,35.844 55.659,36.262 56.082,36.262
  Bottom Layer w0.1: v1(23.575,34.6) 24.4,33.775 37.982,33.775 39.197,32.561 48.18,32.561 v1(49.475,33.855)
VBAT: C87.2 D6.3 U1.T6 | length 12.2
  Top Layer w0.15: v2@58.875,39.933 U1.T6@58.875,40.325
  Bottom Layer w0.3: C87.2@50.485,42.988 50.485,42.185 50.423,42.123 50.423,41.923 50.073,41.573 D6.3@49.873,41.573 50.976,40.471 53.326,40.471 53.642,40.788 55.87,40.788 56.299,40.358 58.427,40.358 v2@58.864,39.921 ; v2@58.831,39.889 v2@58.864,39.921 ; v2(58.875,39.91) v2@58.864,39.921 ; v2@58.875,39.933 v2@58.864,39.921
VDD3V3_USB: C156.2 R286.1 U26.13 | length 50.7
  Top Layer w0.21: U26.13@30.7,40.63 30.7,40.2 31.163,39.737 31.418,39.737 31.42,39.735 31.49,39.735 31.625,39.6 C156.2@31.625,39.53
  Top Layer w0.3: C156.2@31.625,39.53 v3(32.235,39.53)
  Signal Layer 2 w0.3: 43.518,27.562 67.603,27.562 69.284,29.244 v1(69.284,30.569)
  Signal Layer 2 w0.5: v3(32.235,39.53) 35.12,39.53 37.15,37.5 37.15,33.93 43.518,27.562
  Bottom Layer w0.3: R286.1@67.89,31.915 67.898,31.908 68.514,31.908 69.284,31.138 v1(69.284,30.569)
VDD_DDR: C13.2 C39.2 C41.2 C53.2 C55.2 C56.2 C60.2 C62.2 C63.2 C65.2 C67.2 C73.2 C75.2 C76.2 C77.1 C82.2 C83.2 C84.2 C88.2 C150.2 C151.2 C162.2 C194.2 C197.2 C200.2 C202.2 C205.2 C218.2 C219.2 C221.2 L5.2 LNK8.2 R141.2 R146.2 U1.1C11 U1.1D12 U1.1E11 U1.1F12 U1.1L11 U1.1M12 U1.M22 U1.N21 U1.R21 U13.A1 U13.A9 U13.B3 U13.B9 U13.C1 U13.D1 U13.D9 U13.F2 U13.F8 U13.G1 U13.G7 U13.G9 U13.J1 U13.J2 U13.J8 U13.J9 U13.L1 U13.L9 U13.R1 U13.T9 U15.A1 U15.A9 U15.B3 U15.B9 U15.C1 U15.D1 U15.D9 U15.F2 U15.F8 U15.G1 U15.G7 U15.G9 U15.J1 U15.J2 U15.J8 U15.J9 U15.L1 U15.L9 U15.R1 U15.T9 U26.43 | length 81.5
  Top Layer w0.09: U15.J8@85.75,35.174 U15.J8@85.75,35.199 ; U13.G1@105.006,47.75 U13.G1@105.006,47.869 ; U13.A9@109.781,41.502 U13.A9@109.805,41.526
  Top Layer w0.15: v1(16.298,46.165) 16.7,45.763 LNK8.2@16.7,45.723 ; U1.1L11@65.125,39.075 v2(65.75,39) 65.746,38.996 65.746,38.703 65.625,38.582 U1.1M12@65.625,38.575 65.625,38.565 v2@65.9,38.29 ; U1.1E11@65.125,42.075 65.625,42.075 ; U1.1C11@65.125,43.075 65.675,43.075 v2(65.75,43) ; U1.1F12@65.625,41.575 65.625,42.075 ; v2@65.675,42.99 65.675,42.646 65.625,42.597 U1.1D12@65.625,42.575 65.625,42.075 ; 86.006,40.4 87.015,40.4 ; U15.G1@87.381,40.8 87.381,40.773 87.381,40.61 87.936,40.055 U15.F2@88.126,40.055 ; U13.L9@101.806,41.525 101.806,41.55 102.181,41.925 102.956,41.925 U13.J8@103.417,42.386 ; 103.638,47.503 104.647,47.503 ; U13.G1@105.006,47.75 105.522,47.234 105.691,47.234 105.8,47.125 U13.F2@105.806,47.125 ; v4(105.403,43.579) 105.927,43.579 106.206,43.3 106.206,42.825
  Top Layer w0.16: 65.7,42.075 66.125,42.075 U1.N21@66.375,41.825 ; v2(65.75,39) 65.75,39.031 66.071,39.352 66.071,40.221 v2@66.248,40.398 ; v2(66.26,40.398) 66.26,40.463 66.362,40.565 66.362,40.812 U1.R21@66.375,40.825 66.375,41.233 v2(66.364,41.244) 66.364,41.814 U1.N21@66.375,41.825 ; U1.M22@66.875,42.325 U1.N21@66.375,41.825
  Top Layer w0.21: 24.775,46.4 U26.43@25.325,46.4
  Top Layer w0.25: 21.695,47.125 21.699,47.125 21.845,46.979 21.845,46.685 C39.2@21.955,46.575 ; C39.2@22.005,46.575 22.475,46.575 22.65,46.4 24.775,46.4
  Top Layer w0.3: v3@21.444,47.376 21.695,47.125 ; U15.T9@80.181,34.4 80.467,34.114 80.467,33.947 v4(80.458,33.939) ; U15.R1@80.981,40.8 80.962,40.819 80.962,41.19 80.781,41.371 80.781,41.479 80.901,41.599 80.901,41.97 C60.2@81.006,42.075 ; C84.2@83.836,33.16 C84.2@83.874,33.197 ; C62.2@83.931,41.972 83.931,41.493 83.836,41.398 83.836,41.148 84.158,40.825 84.181,40.825 U15.L1@84.181,40.8 ; C84.2@83.948,33.472 84.327,33.85 84.381,33.85 84.342,33.888 84.342,34.211 84.181,34.373 U15.L9@84.181,34.4 ; v4@85.731,33.85 85.781,33.9 U15.J8@85.781,35.2 ; U15.J2@85.781,40 85.8,40.019 85.8,40.092 86.006,40.299 86.006,40.4 86.006,40.547 85.781,40.773 v4@85.781,41.375 ; C63.2@86.67,42.05 86.806,41.914 86.806,41.632 86.881,41.557 86.881,41.504 86.981,41.404 86.981,41.325 87.362,40.944 87.362,40.819 U15.G1@87.381,40.8 ; 87.015,40.4 87.015,40.407 U15.G1@87.381,40.773 ; v4@87.376,33.855 87.381,33.859 87.381,34.4 88.181,35.2 88.175,35.2 88.168,35.2 87.781,35.588 87.781,35.6 87.393,35.987 87.381,35.987 U15.G7@87.381,36 ; U15.D9@89.781,34.4 89.981,34.2 89.981,33.85 89.951,33.82 89.951,33.305 90.306,32.95 C88.2@90.306,32.175 ; U15.D1@89.781,40.8 v4@89.781,41.35 ; U15.C1@90.581,40.8 v4@90.581,41.35 ; v4@90.981,38.8 U15.B3@91.381,39.2 ; U15.B9@91.4,34.348 91.4,34.085 91.556,33.929 v4@91.556,33.875 ; U15.A1@92.181,40.8 v4@92.581,40.4 ; U15.A9@92.2,34.419 92.621,34.419 92.677,34.475 92.702,34.45 v4@92.731,34.45 ; U13.T9@97.812,41.503 98.197,41.119 98.197,41.116 v4(98.152,41.071) ; C151.2@98.055,53.774 98.079,53.749 98.079,53.151 v5(98.104,53.126) ; C56.2@98.58,49.145 98.583,49.148 98.583,48.774 98.332,48.522 v5(98.241,48.522) 98.279,48.484 98.339,48.484 98.605,48.218 U13.R1@98.605,47.92 ; C53.2@101.5,49.15 101.5,48.529 101.492,48.521 101.53,48.483 101.53,48.179 U13.L1@101.789,47.92 ; C67.2@101.549,40.307 101.549,40.544 101.958,40.953 101.978,40.953 v4@101.981,40.95 ; U13.L9@101.812,41.476 101.981,41.308 v4@101.981,40.95 ; v4@101.981,40.925 v4@101.981,40.95 ; v4@103.381,40.975 103.406,41 U13.J9@103.406,41.525 ; U13.J2@103.405,47.12 103.638,47.353 103.638,47.503 103.638,47.687 U13.J1@103.405,47.92 103.606,48.121 v4@103.606,48.475 ; 104.647,47.503 104.647,47.51 U13.G1@105.006,47.869 ; v4@104.806,48.475 105.056,48.725 C55.2@105.056,49.15 ; v4@104.981,40.975 105.006,41 U13.G9@105.006,41.525 ; U13.G7@105.033,43.121 U13.G7@105.082,43.17 ; U13.G7@105.083,43.17 105.364,43.451 105.364,43.541 v4(105.403,43.579) ; U13.F8@105.806,42.325 106.206,42.725 106.206,42.825 ; C73.2@107.006,39.2 107.022,39.217 107.022,40.313 107.022,41.142 107.384,41.503 U13.D9@107.412,41.503 ; U13.D1@107.412,47.903 v4@107.412,48.453 ; U13.C1@108.212,47.903 v4@108.212,48.453 ; v4@108.606,45.925 U13.B3@109.006,46.325 ; U13.B9@109.006,41.525 109.006,41.175 v4@109.181,41 ; v4@109.406,47.525 U13.A1@109.806,47.925 ; U13.A9@109.806,41.525 110.331,41.525 v4@110.356,41.55
  Top Layer w0.64: C202.2@15.975,42.45 C41.2@15.975,43.75 C200.2@15.975,45.05 ; 15.975,45.495 15.975,45.925
  Top Layer w0.8: C202.2@16.2,42.45 L5.2@17.975,42.45
  Signal Layer 2 w0.3: v4@95.889,36.291 v4(95.928,36.329)
  Bottom Layer w0.09: C162.2@110.028,48.204 C162.2@110.053,48.179
  Bottom Layer w0.15: C13.2@65.35,43.425 v2@65.627,43.148 ; C82.2@65.352,41.603 65.452,41.703 65.452,41.862 65.625,42.035 ; 65.625,42.075 65.625,42.143 65.675,42.193 v2@65.675,42.99 ; 66.464,38.973 66.61,39.119 66.61,39.855 C75.2@66.565,39.9
  Bottom Layer w0.16: v2(66.364,41.244) 66.364,40.674 66.271,40.581 66.271,40.421 66.248,40.398 66.248,40.333 66.339,40.242 66.339,40.187 66.47,40.055 66.47,39.995 66.535,39.93 C75.2@66.555,39.93
  Bottom Layer w0.2: v2(65.97,38.26) 65.599,38.26 65.349,38.51 65.349,38.573 65.274,38.648 65.349,38.723 65.463,38.723 65.466,38.726 65.476,38.726 v2(65.75,39) 65.788,38.962 65.922,38.962 66.009,38.875 66.15,38.875 C77.1@66.225,38.8 66.398,38.973 66.464,38.973
  Bottom Layer w0.3: C221.2@72.439,32.556 72.589,32.706 v4(72.589,33.206) ; R141.2@83.272,42.12 83.272,41.917 83.284,41.906 83.295,41.906 83.4,41.801 83.588,41.613 83.588,41.552 83.742,41.398 v4(83.78,41.398) ; C194.2@85.178,42.579 85.566,42.191 ; 85.603,42.154 85.778,41.979 v4(85.778,41.379) ; v4(91.553,33.879) 92.128,34.454 v4(92.728,34.454) ; C205.2@92.053,39.754 92.578,40.279 v4(92.578,40.404) ; C218.2@95.778,35.679 95.928,35.829 v4(95.928,36.329) ; R146.2@100.995,49.275 101.492,48.778 v4@101.492,48.521 ; C150.2@103.363,51.228 103.363,50.7 103.643,50.419 103.643,49.266 ; v4(103.603,48.479) 103.643,48.52 103.643,49.266 ; v4(104.803,48.479) 104.803,48.804 104.341,49.266 103.643,49.266 ; v4(109.403,47.529) 109.403,47.579 C162.2@110.028,48.204 ; v4(110.353,41.554) 110.953,41.554 C197.2@111.003,41.504
  other v1: 15.623,46.165 15.623,46.89 16.298,46.89
  other v3: 21.45,47.348
  other v4: 84.378,33.854 85.728,33.854 87.328,33.854 89.978,33.854 87.778,35.604 90.978,38.804 101.978,40.929 103.378,40.979 104.978,40.979 109.195,41.004 107.028,41.154 86.978,41.354 89.778,41.354 90.578,41.354 80.778,41.429 108.603,45.929 107.413,48.47 108.213,48.479 101.492,48.517
VDD_DDR_FB: LNK8.1 U26.46 | length 10.2
  Top Layer w0.15: LNK8.1@16.7,45.273 16.7,44.19 16.817,44.073 19.267,44.073 19.567,44.373 20.237,44.373 20.239,44.375 22.127,44.375 22.952,45.2 U26.46@25.33,45.2
VDD_EMMC: C9.2 C117.2 C190.1 U26.16 U37.E6 U37.F5 U37.J10 U37.K9 | length 132.1
  Top Layer w0.2: U37.E6@76.425,57.655 76.73,57.655 76.88,57.805 v1(76.975,57.805) 76.975,57.213 76.925,57.163 U37.F5@76.925,57.155 ; v1(78.35,59.055) v1@78.425,59.13 ; U37.J10@78.425,59.655 78.425,59.225 78.417,59.217 78.417,59.138 v1@78.425,59.13 ; U37.K9@78.925,59.155 78.545,59.155 78.512,59.122 78.433,59.122 v1@78.425,59.13
  Top Layer w0.21: U26.16@31.67,41.6 32.1,41.6 32.288,41.412 32.288,41.187 32.434,41.041
  Top Layer w0.25: v3@26.752,33.092 32.549,33.092 36.225,36.768 36.225,37.668 35.912,37.981 C190.1@35.266,37.981 ; 32.432,41.038 32.598,40.872 33.128,40.872 33.525,40.475 33.525,38.925 33.8,38.65 34.695,38.65 35.25,38.095 C190.1@35.25,38.025
  Signal Layer 2 w0.5: v3(26.8,33.125) 26.49,33.435 26.49,34.869 26.957,35.336 26.957,37.177 26.372,37.762 26.372,39.786 25.509,40.649 23.203,40.649 21.327,38.773 12.524,38.773 11.458,39.839 11.458,52.457 20.147,61.146 53.676,61.146 53.869,60.953 73.827,60.953 v1@76.886,57.894 ; v1(76.975,57.805) 76.975,57.819 77.05,57.894 77.05,58.059 77.431,58.44 77.819,58.44 78.2,58.821 78.2,58.891 78.34,59.032 v1@78.34,59.045
  Bottom Layer w0.2: C9.2@76.615,58.58 76.615,58.074 76.884,57.805 v1(76.975,57.805) ; v1(78.35,59.055) 78.35,59.739 C117.2@78.475,59.864
VDD_SDCARD: C142.1 U26.4 | length 5.1
  Top Layer w0.21: 26.925,39.2 27.1,39.375 U26.4@27.1,40.63
  Top Layer w0.3: v3(26.165,36.51) C142.1@26.775,36.51
  Top Layer w0.4: C142.1@26.775,36.51 26.775,37.393 26.51,37.658 26.51,38.785 26.925,39.2
VDDA1V8_AON: C189.2 C234.2 U1.AB3 U1.W2 U26.14 | length 37.9
  Top Layer w0.09: 56.026,38.692 56.705,38.692 56.837,38.825 U1.W2@56.875,38.825 ; v2@57.825,37.775 v2(57.825,37.8)
  Top Layer w0.1: v2(54.932,38.744) 54.99,38.801 55.205,38.801 55.267,38.863 55.805,38.863 55.975,38.692 56.026,38.692
  Top Layer w0.15: U1.AB3@57.375,37.325 v2@57.825,37.775
  Top Layer w0.21: U26.14@31.1,40.63 31.61,40.63 32.148,40.092 32.387,40.092 32.745,39.734 32.745,38.602 33.2,38.147 C189.2@33.2,37.49
  Top Layer w0.3: v3(32.59,37.49) C189.2@33.2,37.49
  Signal Layer 2 w0.2: v2(42.415,36.154) 43.144,35.425 52.627,35.425 53.025,35.823 v2(53.025,35.875)
  Bottom Layer w0.2: v3@32.57,37.493 33.032,37.031 36.158,37.031 37.056,36.133 42.394,36.133 v2(42.415,36.154)
  Bottom Layer w0.3: v2(53.025,35.875) 53.052,35.875 53.152,35.775 53.829,35.775 53.836,35.769 54.451,35.769 54.627,35.944 54.627,36.412 54.891,36.675 55.461,36.675 55.662,36.877 56.088,36.877 57.012,37.8 ; v2(54.932,38.744) 54.936,38.748 C234.2@56.064,38.748 56.199,38.613 56.338,38.613 56.479,38.472 56.479,38.333 57.012,37.8 ; v2(57.825,37.8) 57.012,37.8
